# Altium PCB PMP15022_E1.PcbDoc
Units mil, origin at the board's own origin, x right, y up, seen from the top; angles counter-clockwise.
Board outline 1000 x 1000 mil, 2 copper layers (Top Layer, Bottom Layer), stack 62 mil thick; 38 components, 15 nets, 87 pads, 20 vias.
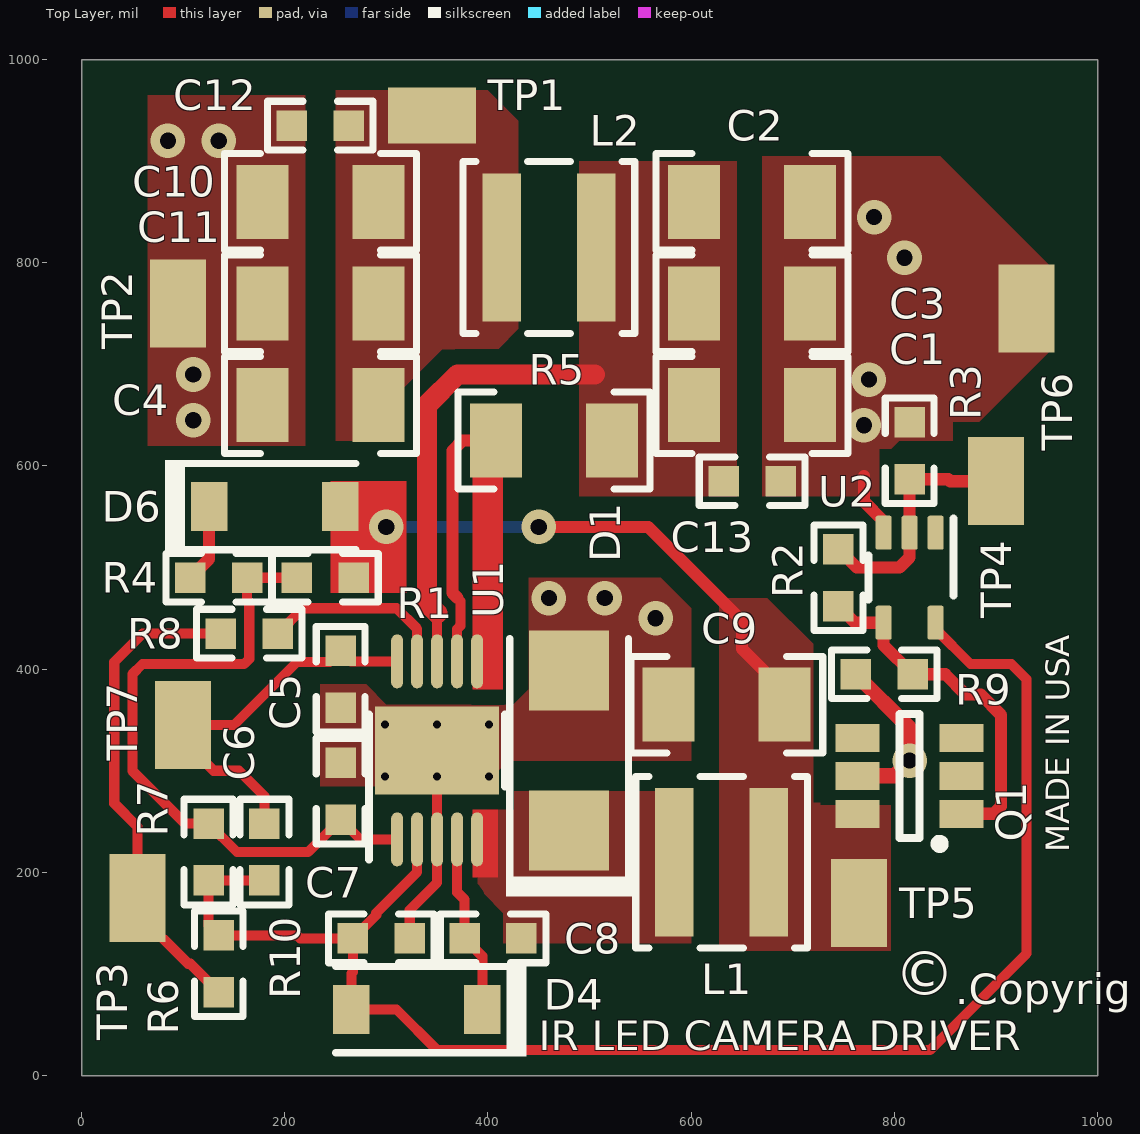
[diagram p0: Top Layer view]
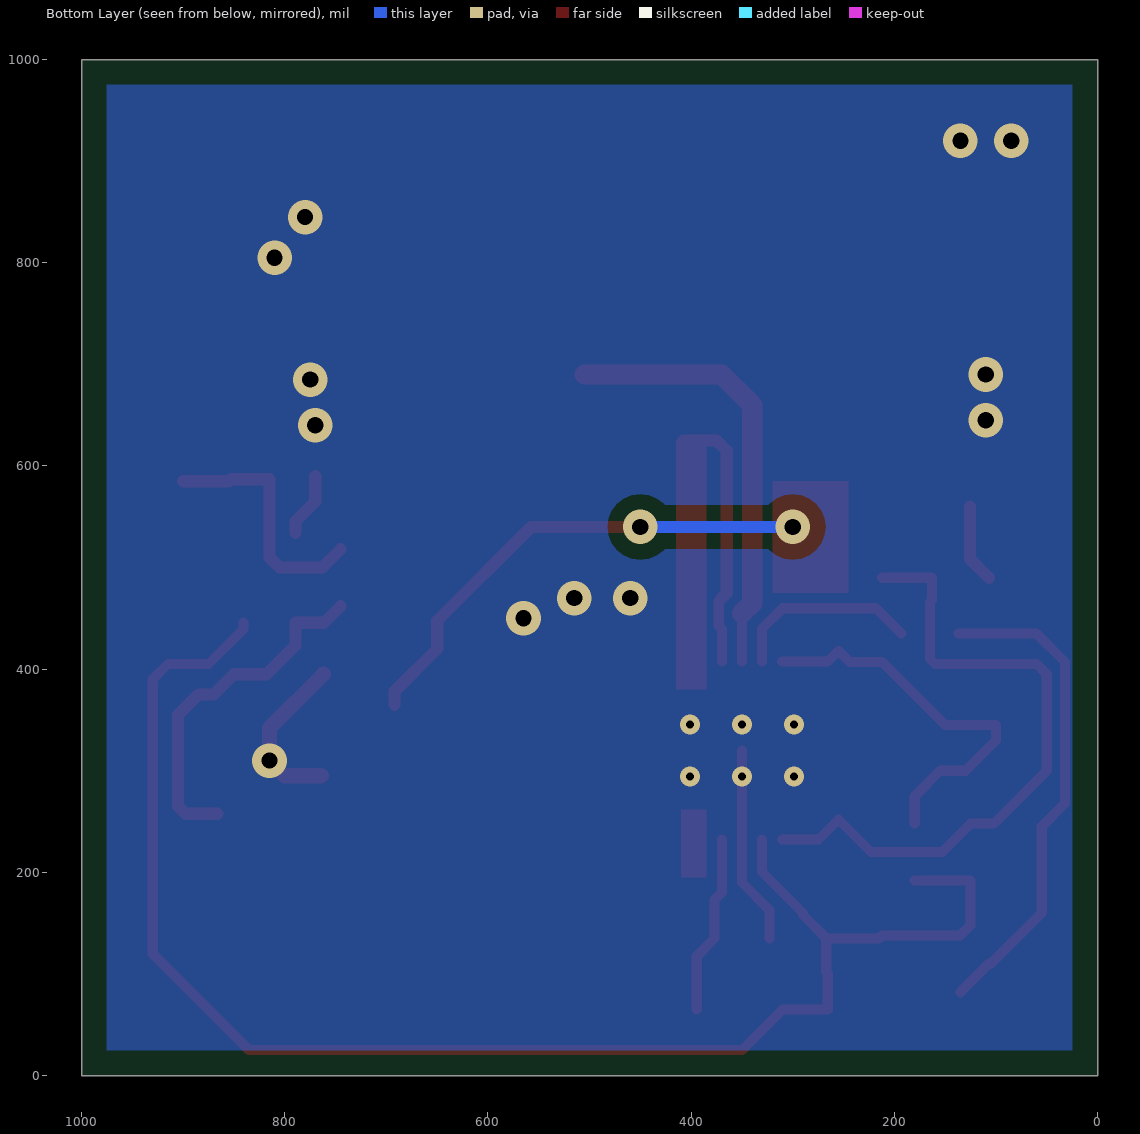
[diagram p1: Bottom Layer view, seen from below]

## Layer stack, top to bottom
Top Solder: solder mask 0.4, Solder Resist, Dk 3.5
Top Layer: signal copper 1.4
Dielectric1: core 59.2, FR-4, Dk 4.8
Bottom Layer: signal copper 1.4
Bottom Solder: solder mask 0.4, Solder Resist, Dk 3.5

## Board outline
0,0 0,1000 1000,1000 1000,0

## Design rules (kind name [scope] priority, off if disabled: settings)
AcuteAngle [All] p1: minimum=4.50000000000000E+0001 checktracksonly=FALSE
AssemblyTestPointUsage [All] p1: valid=2
Clearance Clearance_BoardEdge [OnCopper and Not InComponentClass('Logo') and not InComponentClass('FiducialMark') and not InRegion(1000,500,4000,800) and Not IsKeepout vs IsKeepOut] p1: gap=15
Clearance Clearance_Poly [InPolygon] p2: gap=15
Clearance [All] p3: gap=7.87
ComponentClearance ComponentClearance_Logo [InComponentClass('Logo')] p1: gap=5 collisioncheckmode=3 verticalgap=10 showdistances=FALSE
ComponentClearance [All] p2: gap=5 collisioncheckmode=3 verticalgap=5 showdistances=FALSE
DiffPairsRouting [All] p1: maxlimit=100 minlimit=10 mostfreqgap=10 toplayer_minwidth=15 toplayer_maxwidth=15 toplayer_prefwidth=15 bottomlayer_minwidth=15 bottomlayer_maxwidth=15 bottomlayer_prefwidth=15 maxuncoupledlength=1000
FabricationTestPointUsage TestPointUsage [All] p1: valid=2 allowmultiple=FALSE
FabricationTestpoint Testpoint [All] p1: side=3 testpointundercomponent=TRUE minsize=40 maxsize=100 preferedsize=60 minholesize=0 maxholesize=40 preferedholesize=32 testpointgrid=1 allowsidetop=TRUE allowsidebottom=TRUE usegrid=TRUE gridtolerance=0.01
FanoutControl Fanout_LCC [IsLCC] p1: bgadir=Out bgaviamode=Centered fanoutstyle=Auto fanoutdirection=Alternating viagrid=1 // Fanout_LCC (Default Rule)
FanoutControl Fanout_BGA [IsBGA] p2: bgadir=Out bgaviamode=Centered fanoutstyle=Auto fanoutdirection=Alternating viagrid=1 // Fanout_BGA (Default Rule)
FanoutControl Fanout_Default [All] p4: bgadir=Out bgaviamode=Centered fanoutstyle=Auto fanoutdirection=Alternating viagrid=1 // Fanout_Default (Default Rule)
FanoutControl Fanout_Small [(CompPinCount < 5)] p5: bgadir=Out bgaviamode=Centered fanoutstyle=Auto fanoutdirection=OutThenIn viagrid=1 // Fanout_Small (Default Rule)
HoleSize [All] p1: absolutevalues=TRUE maxlimit=251 minlimit=7.87 maxpercent=80.000 minpercent=20.000
MinimumAnnularRing MinimumAnnularRing_ThermalPadVias [IsVia and InAnyComponent] p1: minimumring=3.94
MinimumAnnularRing [All] p2: minimumring=6.5
MinimumSolderMaskSliver MinimumSolderMaskSliver_Logo [InComponentClass('Logo') vs InComponentClass('Logo')] p1: minsoldermaskwidth=0.7
MinimumSolderMaskSliver [All] p2: minsoldermaskwidth=3.94
PlaneConnect [All] p1: planeconnectstyle=Relief reliefexpansion=10 reliefentries=4 reliefconductorwidth=10 reliefairgap=10
PolygonConnect PolygonConnect_direct [InNet('GND')or InNet('NetDRN_1')or InNet('VIN')or InNet('LED+')or InNet('NetRsense1_1')or InNet('NetR5_1')or InNet('NetC8_1')] p1: connectstyle=Direct reliefconductorwidth=10 reliefentries=4 polygonreliefangle="90 Angle" airgapwidth=10
PolygonConnect [All] p2: connectstyle=Direct reliefconductorwidth=10 reliefentries=4 polygonreliefangle="90 Angle" airgapwidth=10
RoutingVias [All] p1: holewidth=16 width=34 viastyle="Through Hole" minholewidth=7.87 minwidth=15.75 maxholewidth=40 maxwidth=65
SilkToBoardRegionClearance [Not ((IsComment or IsDesignator) And (Hide <> 'False')) and not InRegion(1000,500,4000,800)] p1:
SilkToSilkClearance SilkToSilkClearance_Pb-FreeLogo [(HasFootprint('Pb-Free_Overlay_Medium') OR HasFootprint('Pb-Free_Overlay_Small')) vs (HasFootprint('Pb-Free_Overlay_Medium') OR HasFootprint('Pb-Free_Overlay_Small'))] p1: silktosilkclearance=0
SilkToSilkClearance [All] p2: silktosilkclearance=4
SilkToSolderMaskClearance SilkToSolderMaskClearance_discretes [IsPad AND InAnyComponent] p1: minsilkscreentomaskgap=5 clearancetoexposedcopper=TRUE
SilkToSolderMaskClearance [IsPad] p2: minsilkscreentomaskgap=5 clearancetoexposedcopper=TRUE
SilkToSolderMaskClearance "Silk to Solder Mask Opening" [IsVia vs InComponent('U1')] p3: minsilkscreentomaskgap=-1 clearancetoexposedcopper=FALSE
SolderMaskExpansion [All] p1: expansion=1.97
Width [All] p1: maxlimit=100 minlimit=6 preferedwidth=10 checkconnectedcopper=TRUE
15 further rules are at their usual default settings.

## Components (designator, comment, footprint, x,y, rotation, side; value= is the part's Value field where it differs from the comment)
C1 "GRM31CR61H106KA12L" 1206 660,660 r0 top
C2 "GRM31CR61H106KA12L" 1206 660,860 r0 top
C3 "GRM31CR61H106KA12L" 1206 660,760 r0 top
C4 "GRM31CR61H106KA12L" 1206 235,660 r180 top
C5 "GCM188R71C104KA37J" 0603_HV 255,390 r90 top
C6 "GCM1885C1H471JA16D" 0603_HV 255,280 r90 top
C7 "GCM188R71C105KA64D" 0603_HV 295,135 r0 top
C8 "GCM188R71C104KA37J" 0603_HV 405,135 r180 top
C9 "GRM31CR72A105KA01L" 1206 635,365 r180 top
C10 "GRM31CR61H106KA12L" 1206 235,860 r180 top
C11 "GRM31CR61H106KA12L" 1206 235,760 r180 top
C12 "GRM188R72A104KA35D" 0603_HV 235,935 r180 top
C13 "GRM188R72A104KA35D" 0603_HV 660,585 r0 top
D1 "RB058L-60TE25" SMA 480,320 r90 top
D4 "MMSD4148T1G" SOD-123 330,65 r180 top
D6 "MMSD4148T1G" SOD-123 190,560 r0 top
L1 "XAL4040-103MEB" XAL4040 630,210 r0 top
L2 "XAL4040-103MEB" XAL4040 460,815 r0 top
Q1 "FDC6305N" SSOT-6 815,295 r180 top
R1 "RC0603FR-0719K1L" 0603_HV 240,490 r180 top
R2 "CRCW06030000Z0EA" 0603_HV 745,490 r270 top
R3 "CRCW0603100KFKEA" 0603_HV 815,615 r270 top
R4 "RC0603FR-0719K1L" 0603_HV 135,490 r180 top
R5 "PT1206FR-070R165L" 1206 465,625 r0 top
R6 "CRCW060310K0FKEA" 0603_HV 135,110 r270 top
R7 "CRCW0603110KFKEA" 0603_HV 125,220 r90 top
R8 "CRCW060310K0FKEA" 0603_HV 165,435 r0 top
R9 "CRCW060310K0FKEA" 0603_HV 790,395 r0 top
R10 "CRCW0603100KFKEA" 0603_HV 180,220 r270 top
TP1 "TESTPOINT" Harwin_S2751-46R 345,945 r180 top
TP2 "TESTPOINT" Harwin_S2751-46R 95,760 r270 top
TP3 "TESTPOINT" Harwin_S2751-46R 55,175 r90 top
TP4 "TESTPOINT" Harwin_S2751-46R 900,585 r90 top
TP5 "TESTPOINT" Harwin_S2751-46R 765,170 r270 top
TP6 "TESTPOINT" Harwin_S2751-46R 930,755 r270 top
TP7 "TESTPOINT" Harwin_S2751-46R 100,345 r90 top
U1 "TPS92515DGQR" DGQ0010E_N 350,320 r90 top
U2 "SN74LVC1G17DCKR" DCK0005A_N 815,490 r270 top

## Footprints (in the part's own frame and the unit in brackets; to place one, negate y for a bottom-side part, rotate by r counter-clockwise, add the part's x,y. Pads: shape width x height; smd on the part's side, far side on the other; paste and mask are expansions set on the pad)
0603_HV [mil] "Ernesto recommended land pattern.  26 mil between pads."
  rect 30x30 smd: 1(-28,0) 2(28,0)
  silkscreen extent -52,-24 52,24, body extent -34,-19 34,19, height 39
1206 [mm] "1206 from SM-752 data"
  rect 1.3x1.85 smd: 1(-1.45,0) 2(1.45,0)
  silkscreen extent -2.4,-1.21 2.4,1.21, body extent -1.7,-0.9 1.7,0.9, height 1.35
DCK0005A_N [mm] "SOT353, 5-Leads, Body 2x1.3mm, Pitch 0.65mm, Lead Span 2.1mm, IPC Medium Density"
  rrect25% 0.85x0.4 smd: 1(-1.125,0.65) 2(-1.125,0) 3(-1.125,-0.65) 4(1.125,-0.65) 5(1.125,0.65)
  silkscreen extent -1.48,-1.02 0.55,1.1, body extent -1.14,-1 1.14,1, height 0.95
DGQ0010E_N [mm] "TSSOP, 10-Leads, Body 3x3mm, Pitch 0.5mm, Thermal Pad 1.83x2.1mm, IPC Medium Density"
  rrect5% 1.83x2.1 on Top Solder: 0(0,0)
  rrect5% 1.83x2.1 on Top Paste: 0(0,0)
  rrect100% 1.35x0.3 smd: 1(-2.225,1) 2(-2.225,0.5) 3(-2.225,0) 4(-2.225,-0.5) 5(-2.225,-1) 6(2.225,-1) 7(2.225,-0.5) 8(2.225,0) 9(2.225,0.5) 10(2.225,1)
  rect 2.2x3.1 smd paste-1.1 mask-1.1: 11(0,0)
  silkscreen extent -2.73,-1.7 0.9,1.7, body extent -2.46,-1.5 2.46,1.5, height 0.95
Harwin_S2751-46R [mm] "Test Point, SMT"
  rect 2.2x1.4 smd: 1(0,0)
  body extent -1,-0.6 1,0.6, height 1.4
SMA [mm] "Molded Diode, 2-Leads, Body 4.3x2.6mm, IPC Medium Density, based on OnSemi component dimensions and land pattern"
  rect 2x2 smd: 1(-2,0) 2(2,0)
  silkscreen extent -3.66,-1.57 2.79,1.57, body extent -2.6,-1.3 2.6,1.3, height 2.42
SOD-123 [mm] "On Semi recommended land pattern"
  rect 0.915x1.22 smd: 1(-1.637,0) 2(1.637,0)
  silkscreen extent -2.74,-1.17 2.03,1.17, body extent -1.93,-0.9 1.93,0.9, height 1.35
SSOT-6 [mm] "Fairchild"
  rect 1.1x0.7 smd: 1(-1.3,0.95) 2(-1.3,0) 3(-1.3,-0.95) 4(1.3,-0.95) 5(1.3,0) 6(1.3,0.95)
  silkscreen extent -0.85,-1.55 0.25,1.8, body extent -1.5,-1.5 1.5,1.5, height 1.1
XAL4040 [mil] "Coilcraft XAL4040 7/18/12"
  rect 38x146 smd: 1(-46.5,0) 2(46.5,0)
  silkscreen extent -84,-84 84,84, body extent -84,-84 84,84, height 161

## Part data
C1 C2 C3 C4 C10 C11: "CAP, CERM, 10 µF, 50 V, +/- 10%, X5R, 1206"
C5 C8: "CAP, CERM, 0.1 µF, 16 V, +/- 10%, X7R, 0603_095"
C6: "CAP, CERM, 470 pF, 50 V, +/- 5%, C0G/NP0, 0603_095"
C7: "CAP, CERM, 1 µF, 16 V, +/- 10%, X7R, 0603_095"
C9: "CAP, CERM, 1 µF, 100 V, +/- 10%, X7R, 1206"
C12 C13: "CAP, CERM, 0.1 µF, 100 V, +/- 10%, X7R, 0603"
D1: "Diode, Schottky, 60 V, 3 A, AEC-Q101, SMA"
D4 D6: "Diode, Switching, 100 V, 0.2 A, SOD-123"
L1 L2: "Inductor, Shielded, Composite, 10 µH, 3 A, 0.084 ohm, SMD"
Q1: "MOSFET, N-CH, 20 V, 2.7 A, SSOT-6"
R1 R4: "RES, 19.1 k, 1%, 0.1 W, 0603"
R2: "RES, 0, 5%, 0.1 W, 0603"
R3 R10: "RES, 100 k, 1%, 0.1 W, 0603"
R5: "RES, 0.165, 1%, 0.25 W, 1206"
R6 R8 R9: "RES, 10.0 k, 1%, 0.1 W, 0603"
R7: "RES, 110 k, 1%, 0.1 W, 0603"
TP1 TP2 TP3 TP4 TP5 TP6 TP7: library part S2751-46R, "Test Point, SMT"
U1: "2-A, Buck LED Driver with Integrated N-channel FET, High-Side Current Sense, and Shunt FET PWM Dimming Capability, DGQ0010E (VSSOP-10)"
U2: "SINGLE SCHMITT-TRIGGER BUFFER, DCK0005A (SOT-5)"

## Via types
v1: diameter 34, hole 16, Top Layer to Bottom Layer, 14 vias
v2: diameter 19.68, hole 7.87, Top Layer to Bottom Layer, tented both sides, 6 vias

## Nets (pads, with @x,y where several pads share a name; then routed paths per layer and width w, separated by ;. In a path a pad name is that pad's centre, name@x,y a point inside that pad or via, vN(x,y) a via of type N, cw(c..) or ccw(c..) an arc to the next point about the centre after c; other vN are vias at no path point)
GND: C1.2 C2.2 C3.2 C4.2 C5.1 C6.2 C7.2 C9.2 C10.2 C11.2 C12.2 C13.2 D1.2 Q1.5 R3.1 R9.1 TP2.1 TP6.1 U1.3 U1.11 U2.3 | length 424.3
  Top Layer w10: C7.2 323,163 350,190 U1.3 U1.11
  Top Layer w12: 770,590 770,565 789.41,545.59 U2.3
  Top Layer w15: R9.1 815,342 v1(815,310) 800,295 Q1.5
  other v1: 565,450 460,470 515,470 770,640 110,645 775,685 110,690 810,805 780,845 85,920 135,920
  other v2: 298.82,294.41 350,294.41 401.18,294.41 298.82,345.59 350,345.59 401.18,345.59
IADJ: C5.2 R10.1 TP7.1 U1.10 | length 390
  Top Layer w10: R10.1 180,275 155,300 130,300 100,330 TP7.1 150,345 212,407 244,407 C5.2 265.4,407.6 U1.10
LED+: C9.1 D6.2 L1.2 Q1.6 R1.1 TP5.1 | length 488.4
  Top Layer w12: v1(450,540) 557.76,540 650,447.76 650,420 692.09,377.91 C9.1
  Bottom Layer w12: v1(300,540) v1(450,540)
NetC4_1: C4.1 C10.1 C11.1 C12.1 L2.1 TP1.1
NetC6_1: C6.1 R1.2 R4.1 R7.2 U1.1 | length 661.2
  Top Layer w10: R1.2 R4.1 163,468 165,466 165,410 160,405 60,405 50,395 50,300 102,248 R7.2 153,220 223,220 C6.1 274.6,232.4 U1.1
NetC8_1: C8.1 D1.1 L1.1 U1.5
NetC8_2: C8.2 D4.1 U1.4 | length 177.7
  Top Layer w10: U1.4 369.68,180.32 377,173 C8.2 394.47,117.53 D4.1
NetD6_1: D6.1 R4.2 | length 77.7
  Top Layer w12: R4.2 125.53,508.53 D6.1
NetQ1_1: Q1.1 R2.2 R9.2 U2.4 | length 349.2
  Top Layer w12: R2.2 761.29,445.71 U2.4 789.41,423.59 R9.2 850,395 870,375 885,375 905,355 905,265 897.6,257.6 Q1.1
NetR2_1: R2.1 R3.2 TP4.1 U2.2 | length 244.4
  Top Layer w12: R2.1 763,500 805,500 815,510 U2.2 R3.2 853.01,587 855,585 TP4.1
NetR5_1: R5.1 U1.6 U1.7 | length 259
  Top Layer w10: U1.7 369.68,439.46 372.87,442.65 372.87,467.13 370,470
  Top Layer w12: 370,470 365,475 365,615 375,625 R5.1
NetR6_2: R6.2 R8.1 TP3.1 | length 485.3
  Top Layer w10: R6.2 107,110 105,110 55,160 TP3.1 55,245 32.13,267.87 32.13,407.13 60,435 R8.1
NetR8_2: R8.2 U1.9 | length 188.2
  Top Layer w10: R8.2 218,460 310,460 330.31,439.69 U1.9
VCC: C7.1 D4.2 R6.1 R7.1 R10.2 U1.2 U2.5 | length 1547.2
  Top Layer w10: R10.2 152,192 R7.1 125,148 R6.1 212,138 215,135 C7.1 ; U1.2 330.31,200.31 290,160 290,158 C7.1 ; U2.5 840.59,439.41 875,405 915,405 930,390 930,120 835,25 350,25 310,65 D4.2 265.53,100.53 267,102 C7.1
VIN: C1.1 C2.1 C3.1 C13.1 L2.2 R5.2 U1.8 | length 434
  Top Layer w10: U1.8 350,455
  Top Layer w20: 350,455 340,465 340,660 370,690 505,690
pads on no net: Q1.2 Q1.3 Q1.4 U1.0 U2.1

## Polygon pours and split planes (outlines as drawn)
NetC8_1 on Top Layer "NETC8_1_L01_P055" (solid, remove dead copper, pour order 55): 385,260 405,280 600,280 600,130 415,130 415,160 385,190
VIN on Top Layer "VIN_L01_P053" (solid, remove dead copper, pour order 53): 645,570 645,900 490,900 490,570
NetC4_1 on Top Layer "NETC4_1_L01_P051" (solid, remove dead copper, pour order 51): 315,625 315,675 355,715 410,715 430,735 430,940 400,970 250,970 250,625
GND on Top Layer "GND_L01_P049" (solid, remove dead copper, pour order 49): 220,620 220,965 65,965 65,620
GND on Top Layer "GND_L01_P047" (solid, remove dead copper, pour order 47): 670,570 785,570 785,605 805,625 865,625 955,715 955,795 845,905 670,905
GND on Top Layer "GND_L01_P045" (solid, remove dead copper, pour order 45): 600,310 420,310 395,285 235,285 235,385 280,385 300,365 425,365 440,380 440,490 570,490 600,460
LED+ on Top Layer "LED+_L01_P043" (solid, remove dead copper, pour order 43): 796.5,268.5 796.5,122.76 627.76,122.76 627.76,470 675,470 720,425 720,268.5
GND on Bottom Layer "GND_L02_P059" (solid, remove dead copper, pour order 59): 25,975 975,975 975,25 25,25

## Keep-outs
Keep-Out Layer:
  text ".Layer_Name" at 327,-1108.49 h60

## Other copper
Top Layer:
  rectangle net NetC8_1: 385,195 410,261.69
  rectangle net LED+: 245,475 320,585
  rectangle net NetR5_1: 385,380 415,625
  text ".Layer_Name" at 327,-1108.49 h60
Bottom Layer:
  text ".Layer_Name" at 327,-1108.49 h60

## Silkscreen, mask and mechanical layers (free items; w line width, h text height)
Top Overlay:
  text "MADE IN USA" at 980,220 h40 r90
  text ".CopyrightYear" at 860,70 h30
  text "©" at 800,65 h75
  text "IR LED CAMERA DRIVER" at 450,15 h50
  text ".Layer_Name" at 327,-1108.49 h60
Bottom Overlay:
  text ".Layer_Name" at 327,-1108.49 h60
Top Paste:
  text ".Layer_Name" at 327,-1108.49 h60
Bottom Paste:
  text ".Layer_Name" at 327,-1108.49 h60
Top Solder:
  text ".Layer_Name" at 327,-1108.49 h60
  text ".Layer_Name" at 327,-1108.49 h60
Bottom Solder:
  rectangle: 305,224.46 400,407.6
  text ".Layer_Name" at 327,-1108.49 h60
Drill Guide:
  text ".Layer_Name" at 327,-1108.49 h60
M1 Board Outline:
  the board outline again, w7
  text ".Layer_Name" at 327,-1108.49 h60
M2 Board Dimensions:
  text ".Layer_Name" at 327,-1108.49 h60
M3 3D STEP Top:
  text ".Layer_Name" at 327,-1108.49 h60
M4 3D STEP Bottom:
  text ".Layer_Name" at 327,-1108.49 h60
M5 Assembly Top:
  lines w10: -542,-1180.17 6058,-1180.17 ; -542,-976.83 6060,-976.83 ; -542,-773.5 -542,-1383.5 3463,-1383.5 6060,-1383.5 6060,-773.5 -541.5,-773.5 -541.5,-1383.5 1034,-1383.5 ; 1923,-1383.5 1923,-773.5 ; 3190,-976.83 3190,-773.5 ; 4030,-976.83 4030,-773.5 ; 4652,-1390 4652,-1187.17
  text "COMPONENTS MARKED 'DNP' SHOULD NOT BE POPULATED." at 903.5,-568.5 h60
  text "ASSEMBLY VARIANT:" at 903,-684 h60
  text ".VariantName" at 1939,-684 h60
  text "PCB VIEWED FROM TOP SIDE" at -478.5,-905.67 h60
  text "BOARD #:" at 1998,-905.67 h60
  text ".PRJ_Number" at 2543.5,-905.67 h60
  text "REV:" at 3388,-905.67 h60
  text ".PCB_Rev" at 3679.5,-905.67 h60
  text "SVN REV:" at 4226,-905.67 h60
  text ".VersionControl_RevNumber" at 4732,-905.67 h60
  text "TID #:" at 1998,-1109 h60
  text ".TID" at 2543.5,-1109 h60
  text "PLOT NAME =" at -478.5,-1314.34 h60
  text ".plot_File_Name" at 327,-1314.34 h60
  text "GENERATED    :" at 2000,-1314.34 h60
  text ".Print_Date" at 2869.5,-1314.34 h60
  text ".Print_Time" at 3598.5,-1314.34 h60
  text "TEXAS INSTRUMENTS" at 4863,-1314.34 h60
M6 Assembly Bottom:
  lines w10: -542.5,-977.33 6059.5,-977.33 ; -540.5,-1180.67 6059.5,-1180.67 ; 865.5,-1390.5 865.5,-1187.67 ; 1487.5,-977.33 1487.5,-774 ; 2327.5,-977.33 2327.5,-774 ; 3594.5,-1384 3594.5,-774 ; 4483.5,-1384 6059,-1384 6059,-774 -542.5,-774 -542.5,-1384 2054.5,-1384 6059.5,-1384 6059.5,-774
  text "COMPONENTS MARKED 'DNP' SHOULD NOT BE POPULATED." at 5852,-568 h60
  text ".VariantName" at 4808,-684 h60
  text "ASSEMBLY VARIANT:" at 5847,-684 h60
  text ".VersionControl_RevNumber" at 785.5,-906.17 h60
  text "SVN REV:" at 1291.5,-906.17 h60
  text ".PCB_Rev" at 1838,-906.17 h60
  text "REV:" at 2129.5,-906.17 h60
  text ".PRJ_Number" at 2974,-906.17 h60
  text "BOARD #:" at 3519.5,-906.17 h60
  text "PCB VIEWED FROM BOTTOM SIDE" at 5996,-906.17 h60
  text ".TID" at 2974,-1109.5 h60
  text "TID #:" at 3519.5,-1109.5 h60
  text "TEXAS INSTRUMENTS" at 654.5,-1314.84 h60
  text ".Print_Time" at 1919,-1314.84 h60
  text ".Print_Date" at 2648,-1314.84 h60
  text "GENERATED    :" at 3517.5,-1314.84 h60
  text ".plot_File_Name" at 5190.5,-1314.84 h60
  text "PLOT NAME =" at 5996,-1314.84 h60
M9 Title Sheet:
  drawing of 57 lines, arcs and shapes, not listed
  text "1" at 489.84,7786.5 h70
  text "2" at 2985.5,7786.5 h70
  text "3" at 5474.84,7786.5 h70
  text "4" at 7981.51,7786.5 h70
  text "5" at 10480.5,7786.5 h70
  text "6" at 12985.5,7786.5 h70
  text "A" at -666.5,6643.5 h70
  text "A" at 14133.5,6643.5 h70
  text "B" at -666.5,4263.5 h70
  text "B" at 14133.5,4263.5 h70
  text "C" at -666.5,1888.5 h70
  text "C" at 14133.5,1888.5 h70
  text "PROJECT TITLE:" at 11093.5,27.5 h45
  text ".PRJ_Title" at 11143.5,-105.83 h70
  text "DESIGNED FOR:" at 11093.5,-273.5 h45
  text ".PRJ_Customer" at 11143.5,-413.5 h70
  text "D" at -666.5,-481.5 h70
  text "D" at 14133.5,-481.5 h70
  text "FILE NAME:" at 11093.5,-573.5 h45
  text ".PCB_File_Name_No_Path" at 11143.5,-693.5 h70
  text "Texas Instruments (TI) and/or its licensors do not warrant the accuracy or completeness of this specification" at 6124,-855.34 h45
  text "ENGINEER:" at 11093.5,-863.5 h45
  text "LAYOUT BY:" at 12598.5,-863.5 h45
  text "or any information contained therein. TI and/or its licensors do not warrant that this design will meet" at 6079.01,-968 h45
  text ".PRJ_Engineer" at 11143.5,-1018.49 h70
  text ".PCB_Layout" at 12649,-1018.49 h70
  text "the specifications, will be suitable for your application or fit for any particular purpose, or will operate in" at 6079.01,-1080.67 h45
  text ".Layer_Name" at 327,-1108.49 h60
  text "ALTIUM DESIGNER VERSION:" at 12598.5,-1173.5 h45
  text "an implementation. TI and/or its licensors do not warrant that the design is production worthy. You should" at 6079.01,-1193.33 h45
  text "completely validate and test your design implementation to confirm the system functionality for your application." at 6124,-1306 h45
  text ".print_Scale" at 11143.5,-1306.83 h70
  text ".Application_BuildNumber" at 12649,-1306.83 h70
  text "1" at 489.84,-1513.5 h70
  text "2" at 2985.5,-1513.5 h70
  text "3" at 5474.84,-1513.5 h70
  text "4" at 7981.51,-1513.5 h70
  text "5" at 10480.5,-1513.5 h70
  text "6" at 12985.5,-1513.5 h70
M10 Fab Notes:
  drawing of 185 lines, arcs and shapes, not listed
  text "DESIGN INFORMATION" at 12131.02,5660 h60
  text "MIN. TRACK WIDTH:" at 11486.46,5480 h60
  text "10" at 12582.7,5480 h60
  text "MIL" at 12737.46,5480 h60
  text "MIN. CLEARANCE:" at 11486.46,5348 h60
  text "0.2" at 12522.7,5348 h60
  text "MM" at 12737.46,5348 h60
  text "MIN. VIA PAD SIZE:" at 11486.46,5216 h60
  text "34" at 12552.71,5216 h60
  text "MIL" at 12737.46,5216 h60
  text "MINIMUM ANNULAR RING" at 11157.23,5070 h60
  text "EXTERNAL" at 12889.46,5070 h60
  text "PER ORDER" at 12287.42,5060.64 h60
  text "PER" at 11357.23,4952 h60
  text "IPC-D-275 CLASS 2 LEVEL C" at 11577.23,4952 h60
  text "PER ORDER" at 13505.42,4834.64 h60
  text "REGISTRATION TOLERANCES:" at 11157.23,4834 h60
  text "METAL" at 12357,4834 h60
  text "PER ORDER" at 12662,4834 h60
  text "HOLES" at 13206,4828 h60
  text "MATERIAL:" at 11082.46,4624.54 h60
  text "FR-4 High Tg" at 12068.9,4484.21 h60
  text "FR-408" at 11503.46,4475.64 h60
  text "OTHER" at 12991.46,4475.64 h60
  text "X" at 11910,4465 h60
  text "62 MIL (1.6mm) +/-10%" at 11823.56,4312.92 h60
  text "THICKNESS:" at 11157.23,4308.64 h60
  text "X" at 11695.4,4308.64 h60
  text "OTHER" at 13108.46,4308.64 h60
  text "TOLERANCE:" at 11157.23,4150.64 h60
  text "ANSI IPC-6012 TYPE 3 CLASS 2" at 12183.48,4150.64 h60
  text "X" at 11993,4001 h60
  text "OTHER +/-" at 12183.46,3994.64 h60
  text "PER ORDER" at 12820.42,3984.64 h60
  text "BOW & TWIST:" at 11157.23,3837.64 h60
  text "ANSI IPC-6012 TYPE 3 CLASS 2" at 12183.48,3837.64 h60
  text "PER ORDER" at 12825.42,3684.64 h60
  text "OTHER +/-" at 12183.46,3679.13 h60
  text "X" at 11999,3678 h60
  text "DRILLING:" at 11082.46,3540.64 h60
  text "REFERENCE:" at 11157.23,3423.64 h60
  text "X" at 11805.46,3423.64 h60
  text "AS SHOWN" at 11992.46,3423.64 h60
  text "X" at 12706.46,3423.64 h60
  text "NC_DRILL FILES" at 12843.46,3423.64 h60
  text "PTH MIN COPPER THICKNESS:" at 11157.23,3265.64 h60
  text "1MIL" at 12644.46,3265.64 h60
  text "OTHER" at 13141.46,3265.64 h60
  text "20-30 um" at 13501.46,3265.64 h60
  text "X" at 13035,3255 h60
  text "BOARD FINISH:" at 11082.46,3106.64 h60
  text "SILKSCREEN:" at 11237.68,2988.64 h60
  text "X" at 12186.46,2988.64 h60
  text "TOP" at 12312.46,2988.64 h60
  text "BOTTOM" at 12823.46,2988.64 h60
  text "SILKSCREEN COLOR:" at 11237.68,2821.64 h60
  text "X" at 12185.42,2821.64 h60
  text "WHITE" at 12312.46,2821.64 h60
  text "OTHER" at 12823.46,2821.64 h60
  text "SOLDER RESIST COLOR:" at 11237.68,2651.64 h60
  text "X" at 11805.42,2492.44 h60
  text "GREEN" at 11932.46,2492.44 h60
  text "BLUE" at 12523.46,2492.44 h60
  text "OTHER" at 13061.46,2492.44 h60
  text "IMMERSION GOLD (ENIG)" at 12143.46,2303.92 h60
  text "ENEPIG" at 13481,2300.64 h60
  text "SURFACE FINISH:" at 11082.46,2299.64 h60
  text "IMM. TIN/SILVER OR EQUIV" at 11412,2142.64 h60
  text "OTHER" at 12843.46,2142.64 h60
  text "X" at 11242.5,2130 h60
  text "X" at 11949,1973 h60
  text "ARRAY/PANEL:" at 11082.46,1963.64 h60
  text "CUT AND TRIM PER MECH LAYER 1" at 12143.46,1959.35 h60
  text "N.C. ROUTE" at 12143.46,1807.64 h60
  text "V. SCORE" at 13009.46,1807.64 h60
  text "CERTIFICATION:" at 11082.46,1670.64 h60
  text "MATERIALS AND WORKMANSHIP FOR ALL PCBS" at 11807.46,1670.64 h60
  text "TO MEET OR EXCEED THE REQUIREMENTS OF:" at 11807.46,1572.64 h60
  text "X" at 11433.96,1436.13 h60
  text "ANSI IPC-A-600F CLASS ->" at 11572.96,1436.13 h60
  text "X" at 13212.02,1436.13 h60
  text "2" at 13330.96,1436.14 h60
  text "1" at 13015.96,1434.64 h60
  text "3" at 13684.96,1434.64 h60
  text "UL 94V-0" at 11572.96,1276.64 h60
  text "X" at 12248.02,1276.64 h60
  text "RoHS" at 12384.96,1276.64 h60
  text "OTHER" at 13029.36,1276.64 h60
  text "X" at 11425,1275 h60
  text "ADDITIONAL REQUIREMENTS:" at 11082.46,1135.64 h60
  text "MICROSECTION:" at 11157.23,1020.64 h60
  text "YES" at 12062.96,1020.64 h60
  text "X" at 12322,876 h60
  text "REQUIRED" at 12924.46,864.49 h60
  text "BARE BOARD ELEC. TEST:" at 11157.23,861.64 h60
  text "NONE" at 12462.96,861.64 h60
  text "PER ORDER" at 13516.46,861.64 h60
  text "MANUFACTURER'S UL:" at 11157.23,704.64 h60
  text "X" at 12695,705 h60
  text "RAIL" at 12322.96,700.35 h60
  text "METAL" at 12814.77,700.35 h60
  text "SILK" at 13326.46,700.35 h60
  text ".Layer_Name" at 327,-1108.49 h60
M11 Gerber Information:
  lines w10: -542,-1180.17 6058,-1180.17 ; -542,-976.83 6060,-976.83 ; -542,-773.5 -542,-1383.5 3463,-1383.5 6060,-1383.5 6060,-773.5 -541.5,-773.5 -541.5,-1383.5 1034,-1383.5 ; 1923,-1383.5 1923,-773.5 ; 3190,-976.83 3190,-773.5 ; 4030,-976.83 4030,-773.5 ; 4652,-1390 4652,-1187.17
  text "ALL ARTWORK VIEWED FROM TOP SIDE" at -478.5,-905.67 h60
  text "BOARD #:" at 1998,-905.67 h60
  text ".PRJ_Number" at 2543.5,-905.67 h60
  text "REV:" at 3388,-905.67 h60
  text ".PCB_Rev" at 3679.5,-905.67 h60
  text "SVN REV:" at 4226,-905.67 h60
  text ".VersionControl_RevNumber" at 4732,-905.67 h60
  text "LAYER NAME =" at -478.5,-1108.49 h60
  text "TID #:" at 1998,-1109 h60
  text ".TID" at 2543.5,-1109 h60
  text "PLOT NAME =" at -478.5,-1314.34 h60
  text ".plot_File_Name" at 327,-1314.34 h60
  text "GENERATED    :" at 2000,-1314.34 h60
  text ".Print_Date" at 2869.5,-1314.34 h60
  text ".Print_Time" at 3598.5,-1314.34 h60
  text "TEXAS INSTRUMENTS" at 4863,-1314.34 h60
M12 Stackup:
  text ".Layer_Name" at 327,-1108.49 h60
M13 Component Bodies Top:
  text ".Layer_Name" at 327,-1108.49 h60
M14 Component Bodies Bottom:
  text ".Layer_Name" at 327,-1108.49 h60
M15 Courtyards Top:
  text ".Layer_Name" at 327,-1108.49 h60
M16 Courtyards Bottom:
  text ".Layer_Name" at 327,-1108.49 h60
Drill Drawing:
  lines w10: 5406.16,2877.68 5419.99,2877.68 5419.99,2863.85 5447.66,2863.85 5447.66,2877.68 5461.49,2877.68 5461.49,2905.35 5447.66,2905.35 5447.66,2919.18 5419.99,2919.18 5419.99,2905.35 5406.16,2905.35 5406.16,2877.68 ; 5406.16,2988.35 5433.82,3002.18 5461.49,2988.35 5447.66,3016.02 5461.49,3043.68 5433.82,3029.85 5406.16,3043.68 5419.99,3016.02 5406.16,2988.35 ; 5417.23,2883.22 5425.52,2883.22 5425.52,2874.92 5442.12,2874.92 5442.12,2883.22 5450.43,2883.22 5450.43,2899.82 5442.12,2899.82 5442.12,2908.12 5425.52,2908.12 5425.52,2899.82 5417.23,2899.82 5417.23,2883.22 ; 5417.23,2999.42 5433.82,3007.72 5450.43,2999.42 5442.12,3016.02 5450.43,3032.62 5433.82,3024.32 5417.23,3032.62 5425.52,3016.02 5417.23,2999.42
  lines w12: 5356,2826.5 7334.44,2826.5 ; 5356,3075.5 7334.44,3075.5 ; 5694.01,2702 5694.01,3200 ; 6026.17,2702 6026.17,3200 ; 6662.65,2702 6662.65,3200 ; 6921.85,2702 6921.85,3200 ; 5356,2702 7334.44,2702 7334.44,3200 5356,3200 5356,2702
  text "Symbol" at 5430.7,3112.85 h72
  text "Quantity" at 5731.36,3112.85 h72
  text "Finished Hole Size" at 6063.52,3112.85 h72
  text "Plated" at 6700,3112.85 h72
  text "Hole Type" at 6959.2,3112.85 h72
  text "6" at 5731.36,2988.35 h60
  text "7.87mil (0.200mm)" at 6063.52,2988.35 h60
  text "PTH" at 6700,2988.35 h60
  text "Round" at 6959.2,2988.35 h60
  text "14" at 5731.36,2863.85 h60
  text "16.00mil (0.406mm)" at 6063.52,2863.85 h60
  text "PTH" at 6700,2863.85 h60
  text "Round" at 6959.2,2863.85 h60
  text "20 Total" at 5731.36,2739.35 h60
  text ".Layer_Name" at 327,-1108.49 h60

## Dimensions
1000,0 to 1000,1000 on M2 Board Dimensions
0,1000 to 1000,1000 on M2 Board Dimensions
